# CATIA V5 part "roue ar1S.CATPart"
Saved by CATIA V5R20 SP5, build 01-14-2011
Part number: roue ar1S
Publications: "Plan.1"
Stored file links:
  U:\think motion\fin\roue ar1S.CATPart
  U:\think motion\fin\squelette.CATProduct
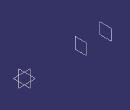
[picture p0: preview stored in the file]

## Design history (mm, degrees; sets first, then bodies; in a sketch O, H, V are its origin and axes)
Set1
  Plane1: linked copy from another document
Set2
  Plane2: type Offset, RefPlane Plane1, Offset 100
Body1 (main body)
